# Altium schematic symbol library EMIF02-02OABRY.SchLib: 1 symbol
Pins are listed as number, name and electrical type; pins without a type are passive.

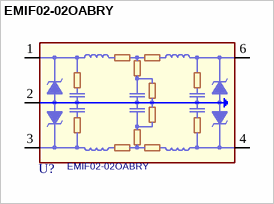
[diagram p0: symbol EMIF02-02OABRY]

## EMIF02-02OABRY
designator U?
footprint ST_QFN110P300X300X85-5L
pins: 1, 2 2/5, 3, 4, 6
